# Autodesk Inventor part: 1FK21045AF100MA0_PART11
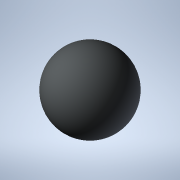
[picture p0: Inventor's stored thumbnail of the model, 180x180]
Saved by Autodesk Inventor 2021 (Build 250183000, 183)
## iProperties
Created: 2025-04
Part Number: 1FK21045AF100MA0_PART11
Material: Generic
Catalog Web Link: www.3dfindit.com
Description: -Servo synchronous motor
Document SubType Name: Modeling
Designer: psAdmin
Mass: 0.137258 g
Surface Area: 1.2868 cm^2
Volume: 0.137258 cm^3
Density: 1 g/cm^3
Appearance: PSOLRGB-212-217-219
Category: PARTsolutions
Title: 1FK21045AF100MA0_PART11
Author: Cadenas PARTsolutions
Comments: Servo synchronous motor
Sending System: PARTsolutions
Preprocessor: ST-DEVELOPER v19.3
PSOL_IDENT_0: {$CADENAS_DATA/23d-libs/siemens_ag/_cat_/52/6b/1fk21045af100ma0.prj},216 {VTYP=3D},{NB=1FK21045AF100
PSOL_IDENT_1: MA0_PART11},{LINA=1FK21045AF100MA0_PART11},{NN=1FK21045AF100MA0_PART11},{NOPRJ=TRUE},{DATE=19.08.202
PSOL_IDENT_2: 5 14:00:38},{GEOMDATE=30.07.2025 02:01:45},{VERSION=},{LINEID=10},{WBVAR=},{WBNUMERIC=}  {NB=1FK2104
PSOL_IDENT_3: 5AF100MA0_PART11},{LINA=1FK21045AF100MA0_PART11},{KT=DUMMY},{PREVIEW=../../../_pool_/cb/72/p_d211_xx
PSOL_IDENT_4: _00434j.png},{DESCSHORT=SIMOTICS S-1FK2 HD, SINAMICS S210 3AC 400V-480V, 2.4 Nm, 3000 rpm},{DESCLONG=
PSOL_IDENT_5: SIMOTICS S-1FK2 HD servo motor M0=2.4 Nm; PN = 0.75 kW at nN=3000 rpm (380-480 V); PN = 0.375 kW at
PSOL_IDENT_6: nN=1500 rpm (200-240 V); with holding brake; degree of protection IP64; cylindrical shaft D19x40mm;
PSOL_IDENT_7: absolute encoder 22-bit + 12-bit multiturn (encoder AM22DQC); with OCC interface; plug size M17, rot
PSOL_IDENT_8: atable; SIMOTICS S-1FK2 servomotorfor a wide range of uses in industrial environments. SIMOTICS S‑1F
PSOL_IDENT_9: K2 servomotors are compact synchronous motors with a high dynamic performance that set themselves ap
PSOL_IDENT_10: art as a result of their high power density, degree of protection and overload capability. The motor
PSOL_IDENT_11: s are available in two variants: as High Dynamic variant (highest dynamic performance as a result of
PSOL_IDENT_12: the low intrinsic moment of inertia for applications demanding a high dynamic performance with low
PSOL_IDENT_13: moved masses) - and as Compact variant (precise and stable closed-loop control for medium up to larg
PSOL_IDENT_14: e moved masses as a result of a medium intrinsic moment of inertia). SIMOTICSS‑1FK2 servomotors full
PSOL_IDENT_15: y exploit their strengths in a system with the SINAMICSS210 frequency converter and simple connectio
PSOL_IDENT_16: n using the one cable connection (OCC). Advantages include the short control and positioning times,
PSOL_IDENT_17: fast and precise correction of disturbing quantities as well as stable control with a high dynamic p
PSOL_IDENT_18: erformance. The servo motors can be configured to address a wide range of requirements. For example
PSOL_IDENT_19: with and without holding brake, IP64 or IP65 degree of protection, singleturn or multiturn absolute
PSOL_IDENT_20: encoders - to name just a few. Further, the servomotors are available in different shaft heights ext
PSOL_IDENT_21: ending from 20 to 100. A shaft sealing ring is available to achieve an IP65 degree of protection and
PSOL_IDENT_22: for subsequent mounting at the motor or as spare part. SIMOTICS - the optimum motor for each and ev
PSOL_IDENT_23: ery motion control application.},{INTNO=804766906411},{SUPPLIERALTNO=1FK2104-5AF10-0MA0},{MANUID=1FK
PSOL_IDENT_24: 21045AF100MA0},{MANUNAME=Siemens},{MANUTYPEDESC=Synchronous motor 1FK2-HD 2.4 NM},{AAU732=SIMOTICS},
PSOL_IDENT_25: {AAO057=S-1FK2},{AAU734=SIMOTICS S-1FK2 HD servo motor M0=2.4 Nm; PN = 0.75 kW at nN=3000 rpm (380-4
PSOL_IDENT_26: 80 V); PN = 0.375 kW at nN=1500 rpm (200-240 V); with holding brake; degree of protection IP64; cyli
PSOL_IDENT_27: ndrical shaft D19x40mm; absolute encoder 22-bit + 12-bit multiturn (encoder AM22DQC); with OCC inter
PSOL_IDENT_28: face; plug size M17, rotatable;},{AAW338=Synchronous motor 1FK2-HD 2.4 NM},{AAO742=SIMOTICS},{AAO663=
PSOL_IDENT_29: 4042948693070},{NOCUPEROU=1},{PRICEQUANTITY=1},{QUANTITYMIN=1},{QUANTITYINT=1},{CTN=85015100},{COO=D
PSOL_IDENT_30: E},{AAO676=1FK2104-5AF10-0MA0},{AAO677=Siemens AG},{ORDERUNIT=C62},{CONTENTUNIT=C62}
NB: 1FK21045AF100MA0_PART11
NT: Servo synchronous motor
NBSYN: $MANUID._PART11
LINA: 1FK21045AF100MA0_PART11
CATALOG: SIEMENS
PREVIEW: ../../../_pool_/cb/72/p_d211_xx_00434j.png
DESCSHORT: SIMOTICS S-1FK2 HD, SINAMICS S210 3AC 400V-480V, 2.4 Nm, 3000 rpm
DESCLONG: SIMOTICS S-1FK2 HD servo motor M0=2.4 Nm; PN = 0.75 kW at nN=3000 rpm (380-480 V); PN = 0.375 kW at nN=1500 rpm (200-240 V); with holding brake; degree of prote
INTNO: 804766906411
SUPPLIERALTNO: 1FK2104-5AF10-0MA0
MANUID: 1FK21045AF100MA0
MANUNAME: Siemens
MANUTYPEDESC: Synchronous motor 1FK2-HD 2.4 NM
AAU732: SIMOTICS
AAO057: S-1FK2
AAU734: SIMOTICS S-1FK2 HD servo motor M0=2.4 Nm; PN = 0.75 kW at nN=3000 rpm (380-480 V); PN = 0.375 kW at nN=1500 rpm (200-240 V); with holding brake; degree of prote
AAW338: Synchronous motor 1FK2-HD 2.4 NM
AAO742: SIMOTICS
AAO663: 4042948693070.0
NOCUPEROU: 1
PRICEQUANTITY: 1
QUANTITYMIN: 1
QUANTITYINT: 1
CTN: 85015100
COO: DE
ARTICLENO: 1FK21045AF100MA0_PART11
BOMINFO: 1FK21045AF100MA0_PART11
CREATOR: CADENAS GmbH
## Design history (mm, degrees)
feature "2025_04_17_15_34_52_0317"
body "Solid1"
